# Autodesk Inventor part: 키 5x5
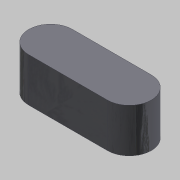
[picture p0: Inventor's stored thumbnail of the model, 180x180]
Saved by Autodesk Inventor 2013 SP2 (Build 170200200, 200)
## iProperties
Created: 2016-04
Part Number: 키 5x5
Document SubType Name: Modeling
Designer: mdu
Density: 7.86 g/cm^3
Mass: 2.54015 g
Surface Area: 2.9781 cm^2
Volume: 0.323175 cm^3
Material: 강철, 연강
Author: mdu
Revision Number: 1
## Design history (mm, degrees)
sketch "스케치1"
  geometry: L1 (-4.5, -2.5)-(4.5, -2.5); L2 (4.5, 2.5)-(-4.5, 2.5); A1 r 2.5 centre (4.5, 0) between (4.5, -2.5) and (4.5, 2.5); A2 r 2.5 centre (-4.5, 0) between (-4.5, 2.5) and (-4.5, -2.5); 2 further points
  constraints: 4 end point, 4 point on circle, 4 tangent, 2 centre point, 1 horizontal, 1 horizontal alignment, 1 midpoint, 1 parallel, 1 vertical alignment
  dimensions: "d0" = 5 distance between parallel lines of L1 L2; "d1" = 14 dimension on A1 A2
extrude "돌출1" new body sketch "스케치1" stored distance "d2" = 5; taper "d3" = 0 deg
node "솔리드1"
